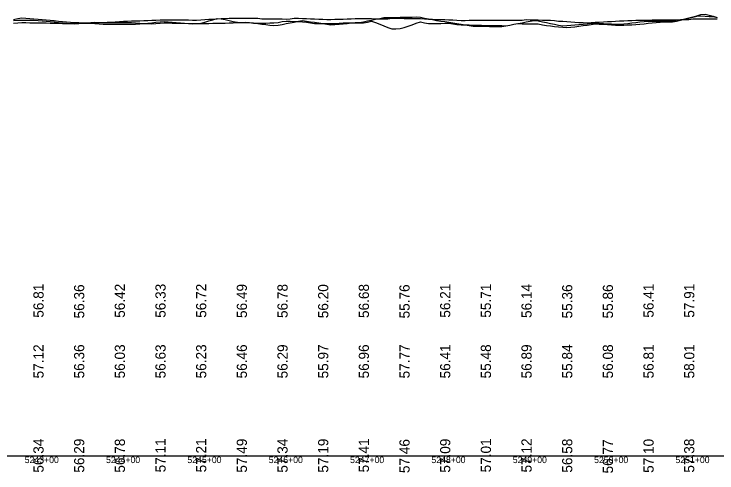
# Model space of a CAD drawing. Extents: x 2147288 to 2220488, y 740833 to 759333.
# Drawn here: x 2206644 to 2207508, y 750062 to 750626 of the extents above; entities that cross this region are included whole.
import ezdxf

# ---------------------------------------------------------------- set-up
doc = ezdxf.new("R2010")
doc.units = 0
for name, color, linetype in [('RD_DDB_Profile_EX', 7, 'Continuous'), ('RD_DDB_StaTX', 7, 'Continuous'), ('RD_DDB_StripGrade', 7, 'Continuous'), ('RD_GPK_Profile_Cell', 7, 'Continuous')]:
    doc.layers.add(name, color=color, linetype=linetype)

msp = doc.modelspace()

# ---------------------------------------------------------------- linework, layer by layer
at = {"layer": 'RD_DDB_Profile_EX'}
for points in [[(2207038.28, 750613.33), (2207043.28, 750613.77), (2207048.28, 750614.2), (2207053.28, 750614.64), (2207058.28, 750615.08), (2207063.28, 750615.52), (2207068.28, 750615.87), (2207073.28, 750616.68), (2207078.28, 750617.68), (2207083.28, 750618.68), (2207088.28, 750619.68), (2207093.28, 750620.68), (2207098.28, 750621.68), (2207103.28, 750622), (2207108.28, 750621.84), (2207113.28, 750621.93), (2207118.28, 750622.02), (2207123.28, 750622.12), (2207128.28, 750622.21), (2207133.28, 750622.3), (2207138.28, 750622.8), (2207143.28, 750622.07), (2207148.28, 750621.12), (2207153.28, 750620.17), (2207158.28, 750619.22), (2207163.28, 750618.28), (2207168.28, 750617.33), (2207173.28, 750616.7), (2207178.28, 750615.94), (2207183.28, 750615.14), (2207188.28, 750614.33), (2207193.28, 750613.53), (2207198.28, 750612.72), (2207203.28, 750611.92), (2207208.28, 750611.33), (2207213.28, 750611.23), (2207218.28, 750611.12), (2207223.28, 750611.01), (2207228.28, 750610.91), (2207233.28, 750610.8), (2207238.28, 750610.7), (2207243.28, 750610.63), (2207248.28, 750611.59), (2207253.28, 750612.55), (2207258.28, 750613.52), (2207263.28, 750614.48), (2207268.28, 750615.44), (2207273.28, 750616.41), (2207278.28, 750617.37), (2207283.28, 750618.27), (2207288.28, 750617.52), (2207293.28, 750616.54), (2207298.28, 750615.55), (2207303.28, 750614.57), (2207308.28, 750613.59), (2207313.28, 750612.6), (2207318.28, 750611.64), (2207323.28, 750611.89), (2207328.28, 750612.35), (2207333.28, 750612.81), (2207338.28, 750613.26), (2207343.28, 750613.72), (2207348.28, 750614.18), (2207353.28, 750614.65), (2207358.28, 750614.63), (2207363.28, 750614.46), (2207368.28, 750614.28), (2207373.28, 750614.11), (2207378.28, 750613.93), (2207383.28, 750613.76), (2207388.28, 750613.57), (2207393.28, 750614.07), (2207398.28, 750614.64), (2207403.28, 750615.22), (2207408.28, 750615.79), (2207413.28, 750616.37), (2207418.28, 750616.95), (2207423.28, 750617.51), (2207428.28, 750617.49), (2207433.28, 750617.44), (2207438.28, 750617.4), (2207443.28, 750617.35), (2207448.28, 750617.3), (2207453.28, 750617.26), (2207458.28, 750617.46), (2207463.28, 750618.78), (2207468.28, 750620.1), (2207473.28, 750621.41), (2207478.28, 750622.72), (2207483.28, 750624.03), (2207488.28, 750625.34), (2207493.28, 750626.03), (2207498.28, 750624.67), (2207503.28, 750623.31), (2207508.28, 750621.95)], [(2206643.28, 750619.5), (2206648.28, 750620.54), (2206653.28, 750621.34), (2206658.28, 750621.01), (2206663.28, 750620.57), (2206668.28, 750620.14), (2206673.28, 750619.7), (2206678.28, 750619.27), (2206683.28, 750618.84), (2206688.28, 750618.39), (2206693.28, 750617.94), (2206698.28, 750617.51), (2206703.28, 750617.07), (2206708.28, 750616.63), (2206713.28, 750616.2), (2206718.28, 750615.76), (2206723.28, 750615.58), (2206728.28, 750615.42), (2206733.28, 750615.09), (2206738.28, 750614.75), (2206743.28, 750614.42), (2206748.28, 750614.08), (2206753.28, 750613.75), (2206758.28, 750613.52), (2206763.28, 750613.54), (2206768.28, 750613.55), (2206773.28, 750613.57), (2206778.28, 750613.59), (2206783.28, 750613.6), (2206788.28, 750613.62), (2206793.28, 750613.51), (2206798.28, 750613.85), (2206803.28, 750614.38), (2206808.28, 750614.9), (2206813.28, 750615.42), (2206818.28, 750615.94), (2206823.28, 750616.47), (2206828.28, 750616.78), (2206833.28, 750616.46), (2206838.28, 750616.09), (2206843.28, 750615.72), (2206848.28, 750615.35), (2206853.28, 750614.99), (2206858.28, 750614.62), (2206863.28, 750614.42), (2206868.28, 750614.47), (2206873.28, 750614.51), (2206878.28, 750614.56), (2206883.28, 750614.6), (2206888.28, 750614.65), (2206893.28, 750614.69), (2206898.28, 750614.83), (2206903.28, 750615), (2206908.28, 750615.18), (2206913.28, 750615.35), (2206918.28, 750615.52), (2206923.28, 750615.7), (2206928.28, 750615.87), (2206933.28, 750615.58), (2206938.28, 750614.95), (2206943.28, 750614.32), (2206948.28, 750613.69), (2206953.28, 750613.05), (2206958.28, 750612.42), (2206963.28, 750611.79), (2206968.28, 750612.43), (2206973.28, 750613.38), (2206978.28, 750614.33), (2206983.28, 750615.27), (2206988.28, 750616.22), (2206993.28, 750617.17), (2206998.28, 750618.07), (2207003.28, 750617.46), (2207008.28, 750616.69), (2207013.28, 750615.93), (2207018.28, 750615.16), (2207023.28, 750614.4), (2207028.28, 750613.63), (2207033.28, 750613), (2207038.28, 750613.33)], [(2206643.28, 750614.82), (2206648.28, 750615.19), (2206653.28, 750615.55), (2206658.28, 750615.72), (2206663.28, 750615.46), (2206668.28, 750615.36), (2206673.28, 750615.26), (2206678.28, 750615.17), (2206683.28, 750615.07), (2206688.28, 750614.97), (2206693.28, 750614.88), (2206698.28, 750614.74), (2206703.28, 750614.51), (2206708.28, 750614.58), (2206713.28, 750614.64), (2206718.28, 750614.71), (2206723.28, 750614.77), (2206728.28, 750614.84), (2206733.28, 750614.91), (2206738.28, 750614.93), (2206743.28, 750614.79), (2206748.28, 750615.15), (2206753.28, 750615.51), (2206758.28, 750615.88), (2206763.28, 750616.24), (2206768.28, 750616.6), (2206773.28, 750616.97), (2206778.28, 750617.32), (2206783.28, 750617.35), (2206788.28, 750617.52), (2206793.28, 750617.68), (2206798.28, 750617.85), (2206803.28, 750618.01), (2206808.28, 750618.18), (2206813.28, 750618.34), (2206818.28, 750618.51), (2206823.28, 750618.95), (2206828.28, 750618.95), (2206833.28, 750618.96), (2206838.28, 750618.96), (2206843.28, 750618.96), (2206848.28, 750618.97), (2206853.28, 750618.97), (2206858.28, 750618.97), (2206863.28, 750618.65), (2206868.28, 750618.71), (2206873.28, 750619), (2206878.28, 750619.29), (2206883.28, 750619.58), (2206888.28, 750619.87), (2206893.28, 750620.16), (2206898.28, 750620.45), (2206903.28, 750620.73), (2206908.28, 750620.91), (2206913.28, 750620.91), (2206918.28, 750620.9), (2206923.28, 750620.9), (2206928.28, 750620.89), (2206933.28, 750620.89), (2206938.28, 750620.88), (2206943.28, 750620.84), (2206948.28, 750620.34), (2206953.28, 750620.27), (2206958.28, 750620.2), (2206963.28, 750620.13), (2206968.28, 750620.06), (2206973.28, 750619.99), (2206978.28, 750619.92), (2206983.28, 750620.32), (2206988.28, 750621.05), (2206993.28, 750620.85), (2206998.28, 750620.65), (2207003.28, 750620.46), (2207008.28, 750620.26), (2207013.28, 750620.06), (2207018.28, 750619.87), (2207023.28, 750619.57), (2207028.28, 750619.26), (2207033.28, 750619.44), (2207038.28, 750619.62)], [(2206643.28, 750618), (2206648.28, 750618.6), (2206653.28, 750618.54), (2206658.28, 750618.49), (2206663.28, 750618.44), (2206668.28, 750618.38), (2206673.28, 750618.16), (2206678.28, 750617.72), (2206683.28, 750617.28), (2206688.28, 750616.79), (2206693.28, 750616.31), (2206698.28, 750615.83), (2206703.28, 750615.34), (2206708.28, 750614.88), (2206713.28, 750614.44), (2206718.28, 750614.15), (2206723.28, 750614.58), (2206728.28, 750615.01), (2206733.28, 750615.43), (2206738.28, 750615.86), (2206743.28, 750616.12), (2206748.28, 750615.79), (2206753.28, 750615.48), (2206758.28, 750615.49), (2206763.28, 750615.5), (2206768.28, 750615.51), (2206773.28, 750615.52), (2206778.28, 750615.53), (2206783.28, 750615.55), (2206788.28, 750615.57), (2206793.28, 750615.25), (2206798.28, 750614.92), (2206803.28, 750614.59), (2206808.28, 750614.27), (2206813.28, 750613.97), (2206818.28, 750614.49), (2206823.28, 750615.01), (2206828.28, 750615.08), (2206833.28, 750615.06), (2206838.28, 750615.04), (2206843.28, 750615.02), (2206848.28, 750615.01), (2206853.28, 750614.65), (2206858.28, 750614.28), (2206863.28, 750614.21), (2206868.28, 750614.26), (2206873.28, 750614.89), (2206878.28, 750616.27), (2206883.28, 750617.64), (2206888.28, 750619.02), (2206893.28, 750620.39), (2206898.28, 750620.24), (2206903.28, 750619.18), (2206908.28, 750618.12), (2206913.28, 750617.06), (2206918.28, 750616), (2206923.28, 750615.87), (2206928.28, 750616.04), (2206933.28, 750615.78), (2206938.28, 750615.15), (2206943.28, 750614.74), (2206948.28, 750614.89), (2206953.28, 750615.04), (2206958.28, 750615.19), (2206963.28, 750615.33), (2206968.28, 750615.81), (2206973.28, 750616.76), (2206978.28, 750617.48), (2206983.28, 750617.23), (2206988.28, 750616.98), (2206993.28, 750616.73), (2206998.28, 750616.48), (2207003.28, 750616.08), (2207008.28, 750615.32), (2207013.28, 750614.61), (2207018.28, 750614.55), (2207023.28, 750614.5), (2207028.28, 750614.44), (2207033.28, 750614.38), (2207038.28, 750614.42)], [(2207038.28, 750614.42), (2207043.28, 750614.86), (2207048.28, 750615.3), (2207053.28, 750615.27), (2207058.28, 750615.23), (2207063.28, 750615.19), (2207068.28, 750615.15), (2207073.28, 750615.25), (2207078.28, 750616.25), (2207083.28, 750617.25), (2207088.28, 750615.47), (2207093.28, 750613.55), (2207098.28, 750611.63), (2207103.28, 750609.71), (2207108.28, 750607.97), (2207113.28, 750608.06), (2207118.28, 750608.16), (2207123.28, 750609.62), (2207128.28, 750611.31), (2207133.28, 750612.99), (2207138.28, 750614.68), (2207143.28, 750616.29), (2207148.28, 750615.34), (2207153.28, 750614.39), (2207158.28, 750614.32), (2207163.28, 750614.46), (2207168.28, 750614.6), (2207173.28, 750614.75), (2207178.28, 750614.89), (2207183.28, 750614.12), (2207188.28, 750613.32), (2207193.28, 750613), (2207198.28, 750612.83), (2207203.28, 750612.66), (2207208.28, 750612.49), (2207213.28, 750612.33), (2207218.28, 750612.21), (2207223.28, 750612.11), (2207228.28, 750612.03), (2207233.28, 750611.96), (2207238.28, 750611.89), (2207243.28, 750611.82), (2207248.28, 750611.75), (2207253.28, 750612.51), (2207258.28, 750613.47), (2207263.28, 750614.25), (2207268.28, 750614.21), (2207273.28, 750614.18), (2207278.28, 750614.15), (2207283.28, 750614.12), (2207288.28, 750613.84), (2207293.28, 750612.86), (2207298.28, 750611.92), (2207303.28, 750611.4), (2207308.28, 750610.87), (2207313.28, 750610.34), (2207318.28, 750609.82), (2207323.28, 750609.48), (2207328.28, 750609.94), (2207333.28, 750610.41), (2207338.28, 750611.13), (2207343.28, 750611.86), (2207348.28, 750612.58), (2207353.28, 750613.3), (2207358.28, 750613.98), (2207363.28, 750613.8), (2207368.28, 750613.63), (2207373.28, 750613.29), (2207378.28, 750612.94), (2207383.28, 750612.59), (2207388.28, 750612.24), (2207393.28, 750612.46), (2207398.28, 750612.73), (2207403.28, 750613.01), (2207408.28, 750613.28), (2207413.28, 750613.6), (2207418.28, 750614.17), (2207423.28, 750614.75), (2207428.28, 750615.2), (2207433.28, 750615.65), (2207438.28, 750616.11), (2207443.28, 750616.56), (2207448.28, 750616.52), (2207453.28, 750616.48), (2207458.28, 750617.41), (2207463.28, 750618.58), (2207468.28, 750619.75), (2207473.28, 750620.92), (2207478.28, 750622.22), (2207483.28, 750623.53), (2207488.28, 750623.81), (2207493.28, 750623.5), (2207498.28, 750623.19), (2207503.28, 750622.87), (2207508.28, 750621.83)], [(2207038.28, 750619.62), (2207043.28, 750619.79), (2207048.28, 750619.97), (2207053.28, 750620.15), (2207058.28, 750620.32), (2207063.28, 750620.58), (2207068.28, 750620.71), (2207073.28, 750620.62), (2207078.28, 750620.52), (2207083.28, 750620.43), (2207088.28, 750620.34), (2207093.28, 750620.25), (2207098.28, 750620.16), (2207103.28, 750620.36), (2207108.28, 750620.86), (2207113.28, 750620.85), (2207118.28, 750620.82), (2207123.28, 750620.79), (2207128.28, 750620.76), (2207133.28, 750620.73), (2207138.28, 750620.7), (2207143.28, 750620.67), (2207148.28, 750620.26), (2207153.28, 750619.9), (2207158.28, 750619.72), (2207163.28, 750619.54), (2207168.28, 750619.36), (2207173.28, 750619.18), (2207178.28, 750619), (2207183.28, 750618.82), (2207188.28, 750618.41), (2207193.28, 750618.28), (2207198.28, 750618.32), (2207203.28, 750618.35), (2207208.28, 750618.39), (2207213.28, 750618.43), (2207218.28, 750618.47), (2207223.28, 750618.5), (2207228.28, 750618.49), (2207233.28, 750618.46), (2207238.28, 750618.46), (2207243.28, 750618.46), (2207248.28, 750618.46), (2207253.28, 750618.46), (2207258.28, 750618.46), (2207263.28, 750618.46), (2207268.28, 750618.64), (2207273.28, 750619.21), (2207278.28, 750619.08), (2207283.28, 750618.94), (2207288.28, 750618.81), (2207293.28, 750618.68), (2207298.28, 750618.54), (2207303.28, 750618.41), (2207308.28, 750618.26), (2207313.28, 750617.48), (2207318.28, 750617.15), (2207323.28, 750616.83), (2207328.28, 750616.5), (2207333.28, 750616.18), (2207338.28, 750615.86), (2207343.28, 750615.53), (2207348.28, 750615.21), (2207353.28, 750615.58), (2207358.28, 750615.88), (2207363.28, 750616.19), (2207368.28, 750616.49), (2207373.28, 750616.79), (2207378.28, 750617.1), (2207383.28, 750617.4), (2207388.28, 750617.7), (2207393.28, 750617.73), (2207398.28, 750618.09), (2207403.28, 750618.22), (2207408.28, 750618.35), (2207413.28, 750618.48), (2207418.28, 750618.61), (2207423.28, 750618.74), (2207428.28, 750618.87), (2207433.28, 750618.97), (2207438.28, 750618.97), (2207443.28, 750619.02), (2207448.28, 750619.06), (2207453.28, 750619.1), (2207458.28, 750619.15), (2207463.28, 750619.19), (2207468.28, 750619.23), (2207473.28, 750619.46), (2207478.28, 750620.33), (2207483.28, 750620.32), (2207488.28, 750620.32), (2207493.28, 750620.31), (2207498.28, 750620.31), (2207503.28, 750620.3), (2207508.28, 750620.3)]]:
    msp.add_lwpolyline(points, dxfattribs=at)
at = {"layer": 'RD_GPK_Profile_Cell'}
msp.add_line((2198888.28, 750083.43), (2220488.28, 750083.43), dxfattribs=at)

# ---------------------------------------------------------------- texts
at = {"layer": 'RD_DDB_Profile_EX'}
for s, p in [('56.81', (2206680.08, 750253)), ('56.36', (2206730.08, 750252.13)), ('56.42', (2206780.08, 750252.89)), ('56.33', (2206830.08, 750252.89)), ('56.72', (2206880.08, 750252.89)), ('56.49', (2206930.08, 750252.64)), ('56.78', (2206980.08, 750252.64)), ('56.20', (2207030.08, 750252.38)), ('56.68', (2207080.08, 750252.64)), ('55.76', (2207130.08, 750252.13)), ('56.21', (2207180.08, 750253)), ('55.71', (2207230.08, 750253)), ('56.14', (2207280.08, 750252.66)), ('55.36', (2207330.08, 750252.13)), ('55.86', (2207380.08, 750252.13)), ('56.41', (2207430.08, 750253)), ('57.91', (2207480.08, 750253)), ('56.34', (2206680.08, 750062.66)), ('56.29', (2206730.08, 750062.64)), ('56.78', (2206780.08, 750062.64)), ('57.11', (2206830.08, 750063)), ('57.21', (2206880.08, 750063)), ('57.49', (2206930.08, 750062.64)), ('57.34', (2206980.08, 750062.66)), ('57.19', (2207030.08, 750062.64)), ('57.41', (2207080.08, 750063)), ('57.46', (2207130.08, 750062.13)), ('57.09', (2207180.08, 750062.64)), ('57.01', (2207230.08, 750063)), ('57.12', (2207280.08, 750062.89)), ('56.58', (2207330.08, 750062.64)), ('56.77', (2207380.08, 750061.67)), ('57.10', (2207430.08, 750062.38)), ('57.38', (2207480.08, 750062.64))]:
    msp.add_text(s, height=12.5, rotation=90, dxfattribs=at).set_placement(p)
at = {"layer": 'RD_DDB_StaTX'}
for s, p in [('5243+00', (2206656.88, 750074.43)), ('5243+00', (2206656.88, 750074.43)), ('5243+00', (2206656.88, 750074.43)), ('5244+00', (2206756.88, 750074.43)), ('5244+00', (2206756.88, 750074.43)), ('5244+00', (2206756.88, 750074.43)), ('5245+00', (2206856.88, 750074.43)), ('5245+00', (2206856.88, 750074.43)), ('5245+00', (2206856.88, 750074.43)), ('5246+00', (2206956.88, 750074.43)), ('5246+00', (2206956.88, 750074.43)), ('5246+00', (2206956.88, 750074.43)), ('5247+00', (2207056.88, 750074.43)), ('5247+00', (2207056.88, 750074.43)), ('5247+00', (2207056.88, 750074.43)), ('5248+00', (2207156.88, 750074.43)), ('5248+00', (2207156.88, 750074.43)), ('5248+00', (2207156.88, 750074.43)), ('5249+00', (2207256.88, 750074.43)), ('5249+00', (2207256.88, 750074.43)), ('5249+00', (2207256.88, 750074.43)), ('5250+00', (2207356.88, 750074.43)), ('5250+00', (2207356.88, 750074.43)), ('5250+00', (2207356.88, 750074.43)), ('5251+00', (2207456.88, 750074.43)), ('5251+00', (2207456.88, 750074.43)), ('5251+00', (2207456.88, 750074.43))]:
    msp.add_text(s, height=8, dxfattribs=at).set_placement(p)
at = {"layer": 'RD_DDB_StripGrade'}
for s, p in [('57.12', (2206680.08, 750178.43)), ('56.36', (2206730.08, 750178.43)), ('56.03', (2206780.08, 750178.43)), ('56.63', (2206830.08, 750178.43)), ('56.23', (2206880.08, 750178.43)), ('56.46', (2206930.08, 750178.43)), ('56.29', (2206980.08, 750178.43)), ('55.97', (2207030.08, 750178.43)), ('56.96', (2207080.08, 750178.43)), ('57.77', (2207130.08, 750178.43)), ('56.41', (2207180.08, 750178.43)), ('55.48', (2207230.08, 750178.43)), ('56.89', (2207280.08, 750178.43)), ('55.84', (2207330.08, 750178.43)), ('56.08', (2207380.08, 750178.43)), ('56.81', (2207430.08, 750178.43)), ('58.01', (2207480.08, 750178.43))]:
    msp.add_text(s, height=12.5, rotation=90, dxfattribs=at).set_placement(p)

doc.saveas('drawing.dxf')
